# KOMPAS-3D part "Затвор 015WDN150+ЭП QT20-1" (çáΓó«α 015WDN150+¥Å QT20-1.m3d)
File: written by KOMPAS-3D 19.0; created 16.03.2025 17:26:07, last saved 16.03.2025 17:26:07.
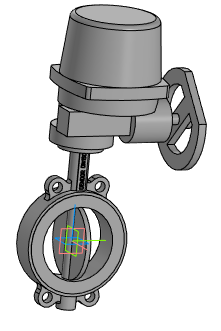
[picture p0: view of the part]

Document properties: Полное имя файла: Затвор 015WDN150+ЭП QT20-1.a3d

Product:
- Part/product: Затвор 015WDN150+ЭП QT20-1
    Масса: 67.6548

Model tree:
1. Операция без истории:1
